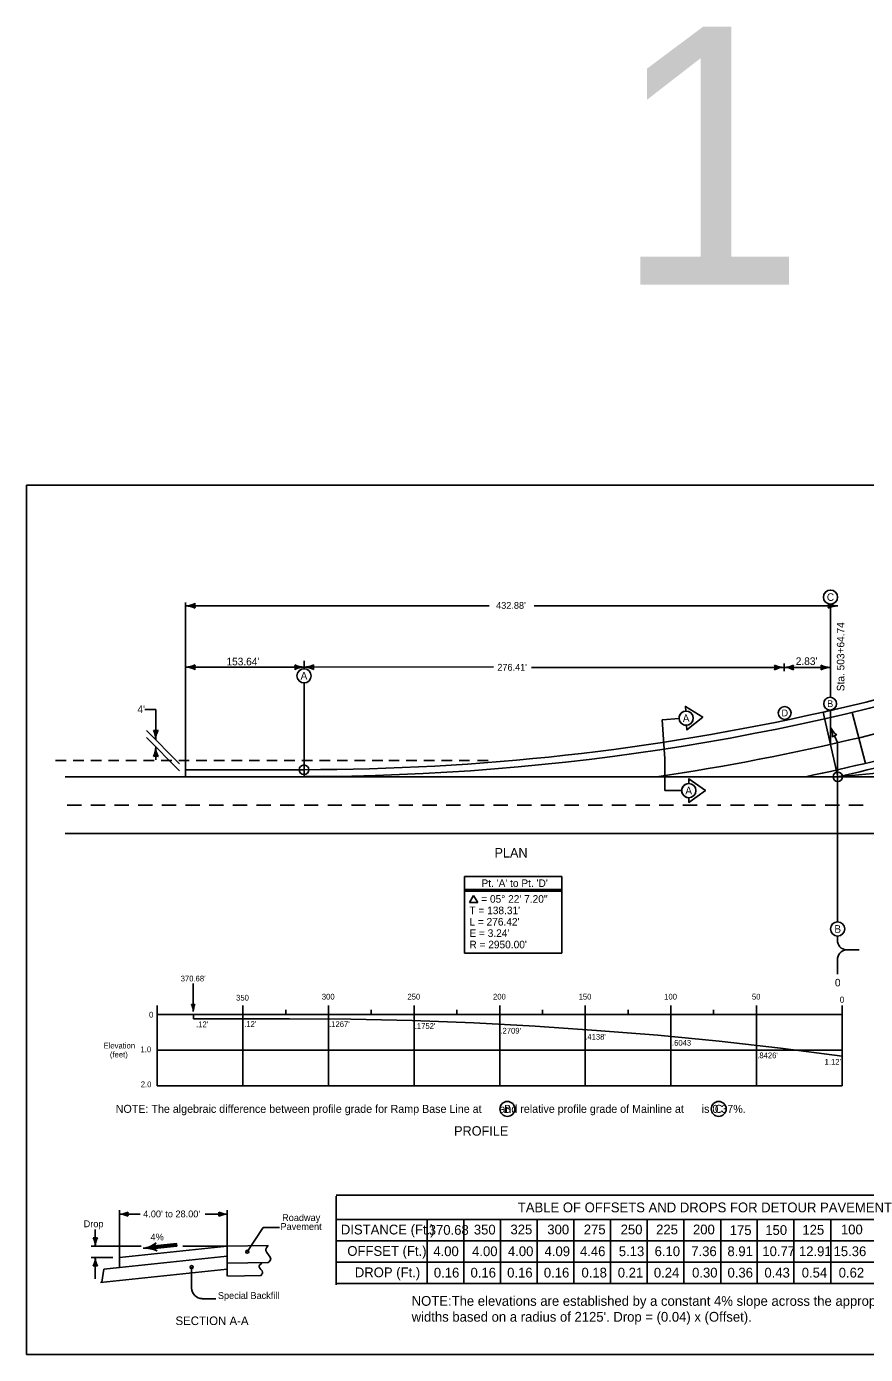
# Model space of a CAD drawing. Extents: x 10133 to 81668, y 4099 to 11018.
# Drawn here: x 10133 to 12081, y 7924 to 11009 of the extents above; entities that cross this region are included whole.
import ezdxf

# ---------------------------------------------------------------- set-up
doc = ezdxf.new("R2010")
doc.units = 0
for name, color, linetype in [('Default', 7, 'Continuous'), ('dsnCellElements', 7, 'Continuous'), ('Level 10', 7, 'Continuous'), ('Level 12', 7, 'Continuous'), ('Level 4', 7, 'Continuous'), ('Level 5', 7, 'Continuous'), ('SheetAddendum', 7, 'Continuous'), ('SheetBorder', 7, 'Continuous'), ('SheetText', 7, 'Continuous'), ('ShtPlotIdentification', 7, 'Continuous')]:
    doc.layers.add(name, color=color, linetype=linetype)

msp = doc.modelspace()

# ---------------------------------------------------------------- linework, layer by layer
at = {"layer": 'Default'}
for p, q in [((12016.5, 9266.1), (11982.7, 9416.4)), ((11982.7, 9416.4), (12016.5, 9266.1)), ((11982.7, 9416.4), (11982.7, 9416.4)), ((12049.8, 9415.5), (12080.7, 9297.3)), ((10488, 9296.5), (10410.7, 9373.8)), ((10488, 9280), (10410.7, 9357.3)), ((12016.5, 9266.1), (10501.9, 9266.1)), ((12016.5, 9266.1), (10501.9, 9266.1)), ((10776.9, 9266.1), (10776.9, 9282.6))]:
    msp.add_line(p, q, dxfattribs=at)
for points in [[(10501.9, 9266.1), (10501.9, 9282.6)], [(10501.9, 9282.6), (10776.9, 9282.6)]]:
    msp.add_lwpolyline(points, dxfattribs=at)
for centre, radius, start, end in [((10776.9, 14783.7), 5517, 270, 288.3725), ((10776.9, 14783.7), 5501.1, 282.6618, 288.3725), ((10776.9, 14783.7), 5578, 278.4444, 288.3725), ((10776.9, 14783.7), 5501.1, 270, 282.6618), ((10776.9, 14783.7), 5501.1, 270, 282.6618), ((10776.9, 14783.7), 5639.1, 281.9188, 288.3725), ((10776.9, 14783.7), 5501.1, 282.6618, 283.0225), ((10776.9, 14783.7), 5655.1, 282.6618, 288.3725), ((11515.8, 14809.9), 5566.3, 275.1605, 280.5457)]:
    msp.add_arc(centre, radius, start, end, dxfattribs=at)
at = {"layer": 'dsnCellElements'}
for p, q in [((12425.9, 8294.3), (10851.2, 8294.3)), ((10851.2, 8291.9), (10851.2, 8086)), ((12425.9, 8237.5), (10851.2, 8237.5)), ((11063.2, 8237.5), (11063.2, 8088.5)), ((11148.4, 8237.5), (11148.4, 8237.5)), ((11148.4, 8237.5), (11148.4, 8088.5)), ((11148.6, 8237.5), (11148.6, 8237.5)), ((11148.8, 8237.5), (11148.8, 8237.5)), ((11149.1, 8237.5), (11149.1, 8237.5)), ((11233.6, 8237.5), (11233.6, 8088.5)), ((11233.6, 8237.5), (11233.6, 8237.5)), ((11233.6, 8237.5), (11233.6, 8088.5)), ((11233.8, 8237.5), (11233.8, 8237.5)), ((11234, 8237.5), (11234, 8237.5)), ((11234.2, 8237.5), (11234.2, 8237.5)), ((11318.7, 8237.5), (11318.7, 8088.5)), ((11403.9, 8237.5), (11403.9, 8088.5)), ((11489.1, 8237.5), (11489.1, 8088.5)), ((11574.2, 8237.5), (11574.2, 8088.5)), ((11659.4, 8237.5), (11659.4, 8088.5)), ((11744.6, 8237.5), (11744.6, 8088.5)), ((11829.7, 8237.5), (11829.7, 8088.5)), ((11914.9, 8237.5), (11914.9, 8088.5)), ((12000.1, 8237.5), (12000.1, 8088.5)), ((12425.9, 8187.8), (10851.2, 8187.8)), ((12425.9, 8138.2), (10851.2, 8138.2)), ((12425.9, 8088.5), (10851.2, 8088.5))]:
    msp.add_line(p, q, dxfattribs=at)
at = {"layer": 'Level 10'}
for p, q in [((12016.1, 9345.8), (12008.6, 9361.6)), ((12016.1, 9345.8), (12016.1, 8929.1)), ((11150, 9034.5), (11150, 8856.5)), ((11150, 9034.5), (11375.5, 9034.5)), ((11375.5, 8856.5), (11375.5, 9034.5)), ((11150, 9004.6), (11375.5, 9004.6)), ((11150, 9000.3), (11375.5, 9000.3)), ((11161, 8974), (11170.9, 8990.5)), ((11170.9, 8990.5), (11180.8, 8974)), ((11180.8, 8974), (11161, 8974)), ((12016.1, 8886.9), (12016.1, 8896.1)), ((11150, 8856.5), (11375.5, 8856.5)), ((12066.1, 8863.7), (12036.5, 8863.7)), ((12016.1, 8840.5), (12016.1, 8807.9)), ((10348.6, 8149.3), (10348.6, 8259.5)), ((10598.7, 8175.4), (10598.7, 8259.5)), ((10515.9, 8126.8), (10515.9, 8078.5)), ((10572.4, 8053.6), (10540.7, 8053.6))]:
    msp.add_line(p, q, dxfattribs=at)
for centre, radius in [((11999.6, 9683.6), 16.5), ((10777.1, 9500.7), 16.5), ((11998.8, 9436), 14.9), ((11893.3, 9414.5), 14.9), ((10776.9, 9282.6), 11), ((12016.5, 9266.1), 11), ((12016.1, 8912.6), 16.5)]:
    msp.add_circle(centre, radius, dxfattribs=at)
for centre, radius, start, end in [((11956.9, 9360.6), 47.3, 357.3748, 25.4473), ((12042.4, 9401.3), 47.3, 205.4473, 233.5198), ((10432.5, 9391.3), 18.1, 252.2666, 287.7334), ((10385.7, 9352), 46.8, 0, 28.0725), ((10479.2, 9352), 46.8, 151.9275, 180), ((12016.7, 9345.1), 18.3, 97.714, 133.1807), ((10385.7, 9335.5), 46.8, 331.9275, 0), ((10479.2, 9335.5), 46.8, 180, 208.0725), ((10432.5, 9296.3), 18.1, 72.2667, 107.7334), ((12038.1, 8885.7), 22, 176.7081, 265.9437), ((12038.1, 8841.8), 22, 94.0563, 183.2919), ((10540.7, 8078.5), 24.8, 180, 270)]:
    msp.add_arc(centre, radius, start, end, dxfattribs=at)
for centre, major_axis, start_param, end_param in [((10519.7, 8750.6), (0, -13.6), 5.97368, 6.592691), ((10485.9, 8721), (0, 35.3), 4.712389, 5.202346), ((10553.5, 8721), (0, -35.3), 4.222432, 4.712389)]:
    msp.add_ellipse(centre, major_axis=major_axis, ratio=0.956827, start_param=start_param, end_param=end_param, dxfattribs=at)
at = {"layer": 'Level 12'}
for centre in [(10645.2, 8162.5), (10515.9, 8126.8)]:
    msp.add_circle(centre, 3.52, dxfattribs=at)
at = {"layer": 'Level 4'}
for p, q in [((11608.5, 9398.6), (11648, 9401.2)), ((11608.5, 9398.6), (11614.6, 9307.7)), ((11614.6, 9307.7), (11614.6, 9234)), ((11614.6, 9234), (11654.2, 9234))]:
    msp.add_line(p, q, dxfattribs=at)
for points in [[(11663.4, 9418.8), (11662.7, 9429.8), (11702.9, 9404.9), (11666.3, 9374.9), (11665.6, 9385.9)], [(11663.4, 9418.8), (11663.4, 9418.8), (11663.4, 9418.8)], [(11670.7, 9250.5), (11670.7, 9261.5), (11709.2, 9234), (11670.7, 9206.5), (11670.7, 9217.5)], [(11670.7, 9250.5), (11670.7, 9250.5), (11670.7, 9250.5)]]:
    msp.add_lwpolyline(points, dxfattribs=at)
for centre, radius in [((11664.5, 9402.3), 16.5), ((11670.7, 9234), 16.5), ((11249.3, 8494.5), 17.4), ((11740, 8494.5), 17.4)]:
    msp.add_circle(centre, radius, dxfattribs=at)
for centre, start, end in [((11664.5, 9402.3), 93.8133, 273.815), ((11664.5, 9402.3), 273.815, 93.8133), ((11670.7, 9234), 89.9992, 270.0008), ((11670.7, 9234), 270.0008, 89.9992)]:
    msp.add_arc(centre, 16.5, start, end, dxfattribs=at)
at = {"layer": 'Level 5'}
for p, q in [((10200, 9304.2), (10224.5, 9304.2)), ((10240.8, 9304.2), (10265.3, 9304.2)), ((10281.7, 9304.2), (10306.2, 9304.2)), ((10281.7, 9304.2), (10306.2, 9304.2)), ((10322.5, 9304.2), (10347, 9304.2)), ((10322.5, 9304.2), (10347, 9304.2)), ((10363.4, 9304.2), (10387.9, 9304.2)), ((10404.2, 9304.2), (10428.8, 9304.2)), ((10445.1, 9304.2), (10469.6, 9304.2)), ((10486, 9304.2), (10510.5, 9304.2)), ((10526.8, 9304.2), (10551.3, 9304.2)), ((10567.7, 9304.2), (10592.2, 9304.2)), ((10608.5, 9304.2), (10633, 9304.2)), ((10649.4, 9304.2), (10673.9, 9304.2)), ((10690.2, 9304.2), (10714.8, 9304.2)), ((10731.1, 9304.2), (10755.6, 9304.2)), ((10772, 9304.2), (10796.5, 9304.2)), ((10812.8, 9304.2), (10837.3, 9304.2)), ((10853.7, 9304.2), (10878.2, 9304.2)), ((10894.5, 9304.2), (10919, 9304.2)), ((10935.4, 9304.2), (10959.9, 9304.2)), ((10973.7, 9304), (10998.2, 9304)), ((11014.5, 9304), (11039, 9304)), ((11055.4, 9304), (11079.9, 9304)), ((11096.2, 9304), (11120.7, 9304)), ((11137.1, 9304), (11161.6, 9304)), ((11179.9, 9303.9), (11204.4, 9303.9)), ((10222.4, 9266.1), (10776.9, 9266.1)), ((12032, 9266.1), (12511.2, 9266.1)), ((10226.8, 9200.1), (10259.8, 9200.1)), ((10281.8, 9200.1), (10314.8, 9200.1)), ((10336.8, 9200.1), (10369.9, 9200.1)), ((10391.9, 9200.1), (10424.9, 9200.1)), ((10446.9, 9200.1), (10479.9, 9200.1)), ((10501.9, 9200.1), (10534.9, 9200.1)), ((10556.9, 9200.1), (10589.9, 9200.1)), ((10611.9, 9200.1), (10644.9, 9200.1)), ((10666.9, 9200.1), (10699.9, 9200.1)), ((10721.9, 9200.1), (10754.9, 9200.1)), ((10776.9, 9200.1), (10809.9, 9200.1)), ((10831.9, 9200.1), (10864.9, 9200.1)), ((10887, 9200.1), (10920, 9200.1)), ((10942, 9200.1), (10975, 9200.1)), ((10997, 9200.1), (11030, 9200.1)), ((11052, 9200.1), (11085, 9200.1)), ((11107, 9200.1), (11140, 9200.1)), ((11162, 9200.1), (11195, 9200.1)), ((11217, 9200.1), (11250, 9200.1)), ((11272, 9200.1), (11305, 9200.1)), ((11327, 9200.1), (11360, 9200.1)), ((11382, 9200.1), (11415.1, 9200.1)), ((11437.1, 9200.1), (11470.1, 9200.1)), ((11492.1, 9200.1), (11525.1, 9200.1)), ((11547.1, 9200.1), (11580.1, 9200.1)), ((11602.1, 9200.1), (11635.1, 9200.1)), ((11657.1, 9200.1), (11690.1, 9200.1)), ((11712.1, 9200.1), (11745.1, 9200.1)), ((11767.1, 9200.1), (11800.1, 9200.1)), ((11822.1, 9200.1), (11855.1, 9200.1)), ((11877.1, 9200.1), (11910.2, 9200.1)), ((11932.2, 9200.1), (11965.2, 9200.1)), ((11987.2, 9200.1), (12020.2, 9200.1)), ((12042.2, 9200.1), (12075.2, 9200.1)), ((10501.9, 9134.1), (10222.4, 9134.1)), ((10501.9, 9134.1), (12511, 9134.1)), ((10519.7, 8785.5), (10519.7, 8721)), ((10436.2, 8714.2), (10436.2, 8735)), ((10635, 8714.2), (10635, 8735)), ((10833.8, 8548), (10833.8, 8735)), ((11032.6, 8548), (11032.6, 8735)), ((11231.4, 8548), (11231.4, 8735)), ((11430.1, 8548), (11430.1, 8735)), ((11628.9, 8548), (11628.9, 8735)), ((11827.7, 8714.2), (11827.7, 8735)), ((12026.5, 8548), (12026.5, 8735)), ((12026.5, 8714.2), (10436.2, 8714.2)), ((10436.2, 8714.2), (10436.2, 8548)), ((10520.3, 8714.2), (10520.3, 8703.8)), ((10520.3, 8703.8), (10600.6, 8703.8)), ((10600.6, 8703.8), (10743.2, 8703.8)), ((10635, 8714.2), (10635, 8548)), ((10734.4, 8714.2), (10734.4, 8724.6)), ((10743.2, 8703.8), (10885.8, 8703)), ((10885.8, 8703), (11028.4, 8699.6)), ((10933.2, 8714.2), (10933.2, 8724.6)), ((11132, 8714.2), (11132, 8724.6)), ((11330.8, 8714.2), (11330.8, 8724.6)), ((11529.5, 8714.2), (11529.5, 8724.6)), ((11728.3, 8714.2), (11728.3, 8724.6)), ((11827.7, 8714.2), (11827.7, 8548)), ((11028.4, 8699.6), (11171, 8694.6)), ((11313.6, 8687), (11171, 8694.6)), ((11456.2, 8676.9), (11313.6, 8687)), ((11598.8, 8665.9), (11456.2, 8676.9)), ((11741.3, 8651.6), (11598.8, 8665.9)), ((11883.9, 8635.6), (11741.3, 8651.6)), ((10436.2, 8631.1), (12026.5, 8631.1)), ((12026.5, 8617), (11883.9, 8635.6)), ((12026.5, 8548), (10436.2, 8548)), ((10645.2, 8162.5), (10681.7, 8219)), ((10681.7, 8219), (10719.6, 8219)), ((10694, 8177.3), (10598.7, 8175.4)), ((10598.7, 8175.5), (10348.6, 8149.3)), ((10348.6, 8126.1), (10598.7, 8152.3)), ((10348.6, 8149.3), (10348.6, 8126.1)), ((10598.7, 8105.9), (10598.7, 8175.5)), ((10598.7, 8122.3), (10304.3, 8091.5)), ((10311.8, 8122.3), (10307, 8091.8)), ((10348.6, 8126.1), (10311.8, 8122.3)), ((10694, 8137.6), (10599.5, 8135.7)), ((10677, 8107.5), (10600.1, 8105.9))]:
    msp.add_line(p, q, dxfattribs=at)
msp.add_lwpolyline([(10501.9, 9282.6), (10776.9, 9282.6)], dxfattribs=at)
msp.add_lwpolyline([(10598.7, 8175.5), (10348.6, 8149.3), (10348.6, 8126.1), (10598.7, 8152.3)], close=True, dxfattribs=at)
for points in [[(10694, 8177.3), (10687.9, 8165.7), (10699.9, 8145.5), (10694, 8137.6)], [(10677, 8107.5), (10680.8, 8115.4), (10672.6, 8127.5), (10680.2, 8137.3)]]:
    msp.add_spline(points, degree=3, dxfattribs=at)
at = {"layer": 'SheetAddendum'}
for p, q in [((10501.9, 9266.1), (10501.9, 9670.9)), ((11207, 9663.2), (10501.9, 9663.2)), ((11311.3, 9663.2), (12016.5, 9663.2)), ((11999.6, 9450.9), (11999.6, 9667.1)), ((10777.1, 9517.2), (10777.1, 9535.7)), ((10502.2, 9521), (10659.6, 9521)), ((10659.6, 9521), (10777.3, 9521)), ((11216.8, 9521.3), (10777.3, 9521)), ((11305.2, 9520.3), (11889.2, 9520.3)), ((11891.8, 9511.2), (11891.8, 9529.7)), ((11891.9, 9520.3), (11953.5, 9520.2)), ((11953.4, 9520.2), (11999.6, 9520.2)), ((10777.3, 9282.6), (10777.3, 9484.2)), ((10432.5, 9422.2), (10407.5, 9422.6)), ((10432.5, 9422.2), (10432.5, 9352)), ((11999.6, 9340.7), (11999.6, 9421.2)), ((10501.9, 9350.8), (10501.9, 9288.8)), ((10432.5, 9305.5), (10432.5, 9335.5)), ((10396, 8249.9), (10348.6, 8249.9)), ((10598.7, 8249.9), (10547, 8249.9)), ((10292.1, 8175.4), (10292.1, 8214.4)), ((10429.3, 8176.6), (10429.3, 8176.6)), ((10429.5, 8173.4), (10481.1, 8178.8)), ((10398.7, 8175.4), (10282.9, 8175.4)), ((10333.2, 8149.3), (10282.9, 8149.3)), ((10292.1, 8099.9), (10292.1, 8149.3)), ((10429.9, 8170.4), (10429.9, 8170.4)), ((10598.4, 8175.4), (10495.4, 8175.4))]:
    msp.add_line(p, q, dxfattribs=at)
for points in [[(10430.3, 8180.4), (10428.5, 8176.6), (10428.7, 8171.4), (10431.1, 8167.1), (10423.1, 8169.5), (10414, 8171.2), (10411.4, 8171.5), (10417.7, 8173.5), (10426.7, 8177.7), (10429.3, 8179.5), (10429.4, 8168.4), (10415.2, 8171.7), (10428.2, 8177.2), (10428.5, 8169.6), (10418.7, 8172.1), (10427.1, 8175.2), (10428, 8170.9), (10421.8, 8172.2), (10426.2, 8174), (10426.7, 8171.9), (10424.4, 8172.3)], [(10429.3, 8176.4), (10480.8, 8181.7), (10481.4, 8175.8), (10429.9, 8170.4), (10429.6, 8175.5), (10480.2, 8181), (10480.6, 8176.3), (10431, 8171.3), (10430.5, 8174.8), (10479.6, 8180.2), (10479.8, 8177), (10431.6, 8172), (10431.2, 8174.2), (10479.1, 8179.4), (10479.2, 8177.7), (10432.1, 8172.8)]]:
    msp.add_lwpolyline(points, dxfattribs=at)
for centre, radius, start, end in [((10501.9, 9709.9), 46.8, 270, 298.0725), ((10501.9, 9616.4), 46.8, 61.9275, 90), ((10541.1, 9663.2), 18.1, 162.2666, 197.7334), ((11977.3, 9663.2), 18.1, 342.2666, 17.7333), ((12016.5, 9709.9), 46.8, 241.9275, 270), ((12016.5, 9616.4), 46.8, 90, 118.0725), ((10502.2, 9567.7), 46.8, 270, 298.0725), ((10502.2, 9474.2), 46.8, 61.9275, 90), ((10541.4, 9521), 18.1, 162.2666, 197.7334), ((10738.1, 9521), 18.1, 342.2667, 17.7334), ((10777.3, 9567.7), 46.8, 241.9275, 270), ((10777.3, 9474.2), 46.8, 90, 118.0725), ((10777.3, 9567.7), 46.8, 270, 298.0725), ((10777.3, 9474.2), 46.8, 61.9275, 90), ((10816.5, 9521), 18.1, 162.2666, 197.7334), ((11852.6, 9520.3), 18.1, 342.2666, 17.7333), ((11891.9, 9567.1), 46.8, 241.9275, 270), ((11891.9, 9473.6), 46.8, 90, 118.0725), ((11891.9, 9567.1), 46.8, 270, 298.0725), ((11891.9, 9473.6), 46.8, 61.9275, 90), ((11931.1, 9520.3), 18.1, 162.2666, 197.7334), ((11960.4, 9520.2), 18.1, 342.2667, 17.7334), ((11999.6, 9567), 46.8, 241.9275, 270), ((11999.6, 9473.4), 46.8, 90, 118.0725), ((10348.6, 8292.1), 42.2, 270, 298.0725), ((10348.6, 8207.7), 42.2, 61.9275, 90), ((10384, 8249.9), 16.3, 162.2666, 197.7334), ((10563.3, 8249.9), 16.3, 342.2667, 17.7334), ((10598.7, 8292.1), 42.2, 241.9275, 270), ((10598.7, 8207.7), 42.2, 90, 118.0725), ((10292.1, 8210.8), 16.3, 252.2667, 287.7334), ((10249.9, 8175.4), 42.2, 0, 28.0725), ((10334.3, 8175.4), 42.2, 151.9275, 180), ((10249.9, 8149.3), 42.2, 331.9275, 0), ((10334.3, 8149.3), 42.2, 180, 208.0725), ((10292.1, 8113.9), 16.3, 72.2666, 107.7334)]:
    msp.add_arc(centre, radius, start, end, dxfattribs=at)
for centre, major_axis, start_param, end_param in [((10394.8, 8234.1), (6.7, -63.7), 0.029395, 0.553518), ((10440.2, 8174.5), (-1.2, 11.1), 0.553526, 2.588067), ((10408.1, 8106.8), (6.7, -63.7), 2.588074, 3.112197)]:
    msp.add_ellipse(centre, major_axis=major_axis, ratio=0.985299, start_param=start_param, end_param=end_param, dxfattribs=at)
at = {"layer": 'SheetBorder'}
msp.add_lwpolyline([(10132.5, 9944), (13267.5, 9944), (13267.5, 7924), (10132.5, 7924)], close=True, dxfattribs=at)
at = {"layer": 'ShtPlotIdentification'}
for p, q in [((10501.9, 9266.1), (10501.9, 9282.6)), ((12016.5, 9266.1), (12032, 9266.1))]:
    msp.add_line(p, q, dxfattribs=at)

# ---------------------------------------------------------------- texts
at = {"layer": 'dsnCellElements'}
for s, height, p in [('TABLE OF OFFSETS AND DROPS FOR DETOUR PAVEMENT', 22.712, (11273.4, 8254.3)), ('DISTANCE (Ft.)', 22.712, (10862.5, 8202.8)), ('370.68', 22.71, (11066.6, 8202)), ('350', 22.71, (11171.3, 8202.7)), ('325', 22.71, (11256.4, 8203)), ('300', 22.71, (11342, 8203)), ('275', 22.71, (11426.7, 8203)), ('250', 22.71, (11512.3, 8203)), ('225', 22.71, (11594.7, 8203)), ('200', 22.71, (11680.3, 8203)), ('175', 22.71, (11765.7, 8201.4)), ('150', 22.71, (11848.2, 8201.7)), ('125', 22.71, (11934.4, 8202.3)), ('100', 22.71, (12023.9, 8203)), ('OFFSET (Ft.)', 22.712, (10877.5, 8153.1)), ('4.00', 22.71, (11077.2, 8152.4)), ('4.00', 22.71, (11167.3, 8152.4)), ('4.00', 22.71, (11250.5, 8152.4)), ('4.09', 22.71, (11335.6, 8152.4)), ('4.46', 22.71, (11417.8, 8152.4)), ('5.13', 22.71, (11508, 8152.4)), ('6.10', 22.71, (11591.2, 8152.4)), ('7.36', 22.71, (11676.3, 8152.4)), ('8.91', 22.71, (11760.3, 8152.4)), ('10.77', 22.71, (11841.4, 8152.4)), ('12.91', 22.71, (11926.4, 8152.4)), ('15.36', 22.71, (12006.8, 8152.4)), ('DROP (Ft.)', 22.71, (10894.9, 8103.4)), ('0.16', 22.71, (11078.4, 8102.7)), ('0.16', 22.71, (11163.6, 8102.7)), ('0.16', 22.71, (11248.7, 8102.7)), ('0.16', 22.71, (11333.9, 8102.7)), ('0.18', 22.71, (11421.3, 8102.7)), ('0.21', 22.71, (11505.6, 8102.7)), ('0.24', 22.71, (11589.4, 8102.7)), ('0.30', 22.71, (11678.2, 8102.7)), ('0.36', 22.71, (11760.5, 8102.7)), ('0.43', 22.71, (11846.2, 8102.7)), ('0.54', 22.71, (11932.9, 8102.7)), ('0.62', 22.71, (12018.7, 8102.7))]:
    msp.add_text(s, height=height, dxfattribs=at).set_placement(p)
at = {"layer": 'Level 10'}
for s, height, p in [('C', 17.6, (11991.2, 9674.8)), ("432.88'", 15.84, (11223.1, 9656.4)), ("153.64'", 17.6, (10596.7, 9525.1)), ("2.83'", 17.6, (11919, 9525.9)), ('A', 17.6, (10768.9, 9491.9)), ("276.41'", 15.84, (11225.9, 9512.6)), ('B', 15.8, (11992, 9428.1)), ('D', 15.8, (11885.9, 9406.6)), ('PLAN', 22, (11219.3, 9078.6)), ("Pt. 'A' to Pt. 'D'", 17.603, (11189, 9010.1)), ("= 05° 22' 7.20''", 17.603, (11188.5, 8973.5)), ("T = 138.31'", 17.603, (11161, 8946.9)), ("L = 276.42'", 17.603, (11161, 8920.5)), ('B', 17.6, (12008.6, 8903.8)), ("E = 3.24'", 17.6, (11161, 8894.1)), ("R = 2950.00'", 17.603, (11161, 8867.6)), ("370.68'", 13.3, (10490.5, 8790.7)), ('0', 17.6, (12009.9, 8779.1)), ('300', 13.3, (10818.3, 8748.6)), ('250', 13.3, (11017.1, 8748.6)), ('200', 13.3, (11215.9, 8748.6)), ('150', 13.3, (11414.7, 8748.6)), ('100', 13.3, (11613.5, 8748.6)), ('50', 13.3, (11817.2, 8748.6)), ('350', 13.3, (10619.2, 8746.2)), ('0', 14.2, (12021.2, 8741.2)), ('0', 13.3, (10417, 8706.8)), (".12'", 13.3, (10526.2, 8684.3)), (".12'", 13.3, (10637.9, 8685.1)), (".1267'", 13.3, (10835.1, 8684.9)), (".1752'", 13.3, (11034.1, 8680.5)), (".2709'", 13.3, (11233, 8669.5)), ('Elevation', 13.3, (10311.4, 8634.9)), ('1.0', 13.3, (10397.2, 8626.2)), (".4138'", 13.3, (11430, 8655.3)), ('.6043', 13.3, (11631.5, 8641.4)), ('(feet)', 13.3, (10326.1, 8614.1)), (".8426'", 13.3, (11829.5, 8612.2)), ("1.12'", 13.3, (11985.9, 8597.1)), ('2.0', 13.3, (10397.8, 8544.9)), ('NOTE: The algebraic difference between profile grade for Ramp Base Line at      and relative profile grade of Mainline at      is 0.37%. ', 18.5883, (10339.6, 8485.3)), ('B', 18.6, (11241.3, 8485.3)), ('C', 18.6, (11731.1, 8485.3)), ('PROFILE', 22, (11125.5, 8432.3)), ('Roadway', 15.89, (10726, 8233.9)), ('Pavement', 15.89, (10722.2, 8213.3)), ('Special Backfill', 15.889, (10576.9, 8053)), ('NOTE:The elevations are established by a constant 4% slope across the appropriate detour', 22.712, (11026.9, 8037)), ("widths based on a radius of 2125'. Drop = (0.04) x (Offset).", 22.712, (11026.9, 8000.1))]:
    msp.add_text(s, height=height, dxfattribs=at).set_placement(p)
msp.add_text('Sta. 503+64.74', height=17.603, rotation=90, dxfattribs=at).set_placement((12032, 9464.9))
at = {"layer": 'Level 4'}
msp.add_text('A', height=17.6, rotation=3.8141, dxfattribs=at).set_placement((11656.9, 9393))
for s, height, p in [('A', 17.6, (11662.4, 9225.2)), ('SECTION A-A', 19.862, (10478.4, 7992.3))]:
    msp.add_text(s, height=height, dxfattribs=at).set_placement(p)
at = {"layer": 'SheetAddendum'}
for s, height, p in [("4'", 17.6, (10389.9, 9414.2)), ("4.00' to 28.00'", 15.889, (10403.4, 8242.5)), ('Drop', 15.89, (10265.1, 8219.6)), ('4%', 15.89, (10420.5, 8188.9))]:
    msp.add_text(s, height=height, dxfattribs=at).set_placement(p)
at = {"layer": 'SheetText'}
msp.add_text('1', height=600, dxfattribs=at).set_placement((11496.6, 10409.2))

doc.saveas('drawing.dxf')
